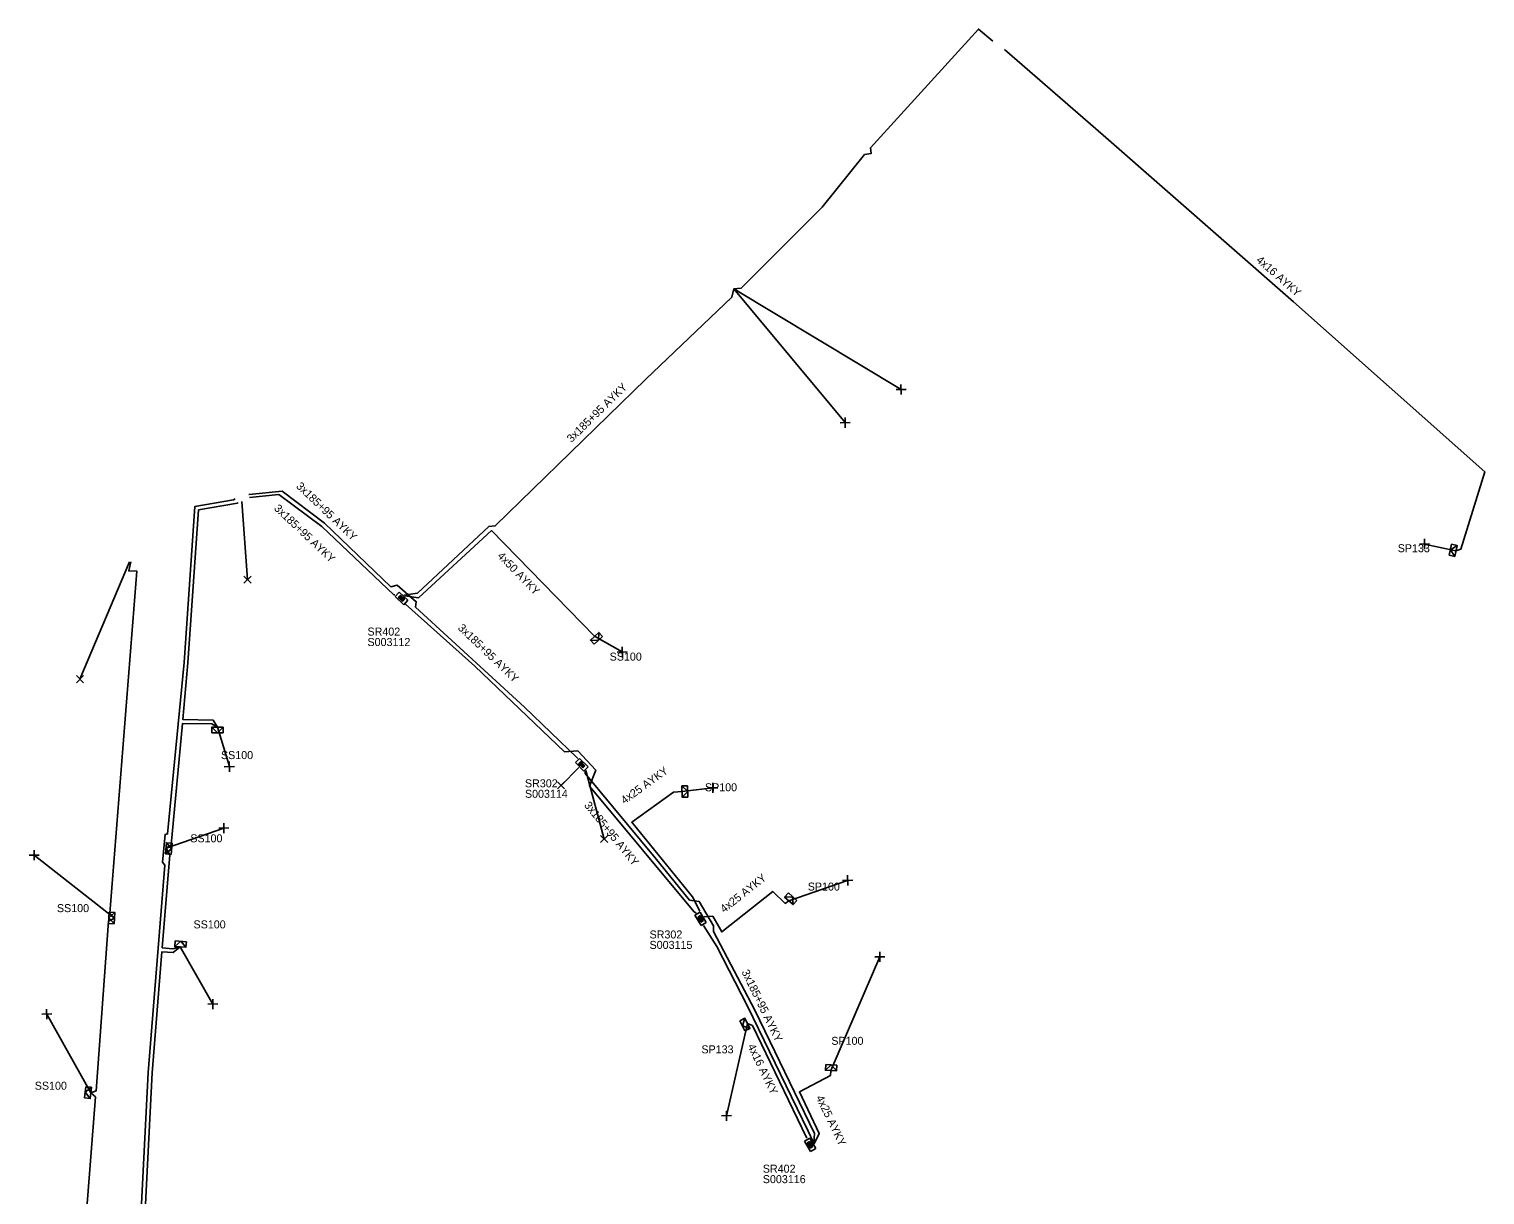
# Model space of a CAD drawing. Extents: x -762894 to -762498, y -1152897 to -1152214.
# Drawn here: x -762770.9 to -762590, y -1152359 to -1152214.1 of the extents above; entities that cross this region are included whole.
import ezdxf

# ---------------------------------------------------------------- set-up
doc = ezdxf.new("R2010")
doc.units = 0
for name, color, linetype in [('Vrstva 28', 7, 'Continuous'), ('Vrstva 29', 7, 'Continuous'), ('Vrstva 30', 7, 'Continuous'), ('Vrstva 31', 7, 'Continuous'), ('Vrstva 33', 7, 'Continuous'), ('Vrstva 34', 7, 'Continuous'), ('Vrstva 5', 7, 'Continuous'), ('Vrstva 59', 7, 'Continuous'), ('Vrstva 6', 7, 'Continuous')]:
    doc.layers.add(name, color=color, linetype=linetype)

msp = doc.modelspace()

# ---------------------------------------------------------------- linework, layer by layer
at = {"layer": 'Vrstva 28'}
for points in [[(-762724.905, -1152284.057), (-762725.416, -1152284.606)], [(-762725.416, -1152284.606), (-762724.319, -1152285.629)], [(-762724.758, -1152284.445), (-762725.015, -1152284.722)], [(-762724.755, -1152284.512), (-762724.949, -1152284.719)], [(-762723.808, -1152285.08), (-762724.905, -1152284.057)], [(-762724.753, -1152284.579), (-762724.882, -1152284.717)], [(-762724.751, -1152284.645), (-762724.815, -1152284.715)], [(-762724.213, -1152284.953), (-762724.758, -1152284.445)], [(-762724.28, -1152284.955), (-762724.755, -1152284.512)], [(-762724.347, -1152284.957), (-762724.753, -1152284.579)], [(-762724.414, -1152284.96), (-762724.751, -1152284.645)], [(-762725.015, -1152284.722), (-762724.471, -1152285.229)], [(-762724.949, -1152284.719), (-762724.473, -1152285.162)], [(-762724.882, -1152284.717), (-762724.476, -1152285.095)], [(-762724.815, -1152284.715), (-762724.478, -1152285.029)], [(-762724.753, -1152284.708), (-762724.476, -1152284.966)], [(-762724.478, -1152285.029), (-762724.414, -1152284.96)], [(-762724.476, -1152285.095), (-762724.347, -1152284.957)], [(-762724.473, -1152285.162), (-762724.28, -1152284.955)], [(-762724.471, -1152285.229), (-762724.213, -1152284.953)], [(-762724.319, -1152285.629), (-762723.808, -1152285.08)], [(-762702.486, -1152304.719), (-762703.017, -1152305.249)], [(-762703.017, -1152305.249), (-762701.956, -1152306.31)], [(-762702.353, -1152305.111), (-762702.62, -1152305.379)], [(-762702.62, -1152305.379), (-762702.094, -1152305.905)], [(-762702.353, -1152305.178), (-762702.553, -1152305.379)], [(-762702.553, -1152305.379), (-762702.094, -1152305.838)], [(-762701.426, -1152305.779), (-762702.486, -1152304.719)], [(-762702.353, -1152305.245), (-762702.486, -1152305.379)], [(-762702.486, -1152305.379), (-762702.094, -1152305.771)], [(-762702.353, -1152305.312), (-762702.419, -1152305.379)], [(-762702.419, -1152305.379), (-762702.094, -1152305.704)], [(-762702.357, -1152305.374), (-762702.09, -1152305.642)], [(-762701.826, -1152305.637), (-762702.353, -1152305.111)], [(-762701.893, -1152305.637), (-762702.353, -1152305.178)], [(-762701.96, -1152305.637), (-762702.353, -1152305.245)], [(-762702.027, -1152305.637), (-762702.353, -1152305.312)], [(-762702.094, -1152305.905), (-762701.826, -1152305.637)], [(-762702.094, -1152305.838), (-762701.893, -1152305.637)], [(-762702.094, -1152305.771), (-762701.96, -1152305.637)], [(-762702.094, -1152305.704), (-762702.027, -1152305.637)], [(-762701.956, -1152306.31), (-762701.426, -1152305.779)], [(-762687.522, -1152323.827), (-762688.165, -1152324.213)], [(-762688.165, -1152324.213), (-762687.392, -1152325.499)], [(-762687.487, -1152324.24), (-762687.811, -1152324.435)], [(-762687.811, -1152324.435), (-762687.428, -1152325.073)], [(-762687.504, -1152324.305), (-762687.746, -1152324.451)], [(-762687.52, -1152324.37), (-762687.682, -1152324.467)], [(-762687.536, -1152324.435), (-762687.617, -1152324.483)], [(-762687.299, -1152324.83), (-762687.536, -1152324.435)], [(-762686.749, -1152325.113), (-762687.522, -1152323.827)], [(-762687.234, -1152324.846), (-762687.52, -1152324.37)], [(-762687.169, -1152324.862), (-762687.504, -1152324.305)], [(-762687.104, -1152324.878), (-762687.487, -1152324.24)], [(-762687.746, -1152324.451), (-762687.412, -1152325.008)], [(-762687.682, -1152324.467), (-762687.396, -1152324.943)], [(-762687.617, -1152324.483), (-762687.38, -1152324.878)], [(-762687.555, -1152324.494), (-762687.36, -1152324.818)], [(-762687.428, -1152325.073), (-762687.104, -1152324.878)], [(-762687.412, -1152325.008), (-762687.169, -1152324.862)], [(-762687.396, -1152324.943), (-762687.234, -1152324.846)], [(-762687.392, -1152325.499), (-762686.749, -1152325.113)], [(-762687.38, -1152324.878), (-762687.299, -1152324.83)], [(-762673.901, -1152351.911), (-762674.551, -1152352.286)], [(-762674.551, -1152352.286), (-762673.801, -1152353.585)], [(-762673.874, -1152352.324), (-762674.201, -1152352.513)], [(-762674.201, -1152352.513), (-762673.829, -1152353.158)], [(-762673.891, -1152352.389), (-762674.136, -1152352.531)], [(-762674.136, -1152352.531), (-762673.812, -1152353.093)], [(-762673.908, -1152352.453), (-762674.072, -1152352.548)], [(-762674.072, -1152352.548), (-762673.794, -1152353.029)], [(-762673.925, -1152352.518), (-762674.007, -1152352.565)], [(-762674.007, -1152352.565), (-762673.777, -1152352.964)], [(-762673.946, -1152352.577), (-762673.757, -1152352.905)], [(-762673.695, -1152352.917), (-762673.925, -1152352.518)], [(-762673.631, -1152352.934), (-762673.908, -1152352.453)], [(-762673.151, -1152353.21), (-762673.901, -1152351.911)], [(-762673.566, -1152352.951), (-762673.891, -1152352.389)], [(-762673.502, -1152352.969), (-762673.874, -1152352.324)], [(-762673.829, -1152353.158), (-762673.502, -1152352.969)], [(-762673.812, -1152353.093), (-762673.566, -1152352.951)], [(-762673.801, -1152353.585), (-762673.151, -1152353.21)], [(-762673.794, -1152353.029), (-762673.631, -1152352.934)], [(-762673.777, -1152352.964), (-762673.695, -1152352.917)]]:
    msp.add_lwpolyline(points, dxfattribs=at)
at = {"layer": 'Vrstva 31'}
for points in [[(-762594.169, -1152278.107), (-762594.46, -1152279.477)], [(-762594.169, -1152278.107), (-762593.484, -1152278.253), (-762593.775, -1152279.622), (-762594.46, -1152279.477)], [(-762594.315, -1152278.792), (-762593.484, -1152278.253)], [(-762594.315, -1152278.792), (-762593.775, -1152279.622)], [(-762700.666, -1152290.531), (-762701.143, -1152290.019), (-762700.119, -1152289.064), (-762699.642, -1152289.576)], [(-762700.154, -1152290.054), (-762701.143, -1152290.019)], [(-762700.666, -1152290.531), (-762699.642, -1152289.576)], [(-762700.154, -1152290.054), (-762700.119, -1152289.064)], [(-762747.483, -1152301.55), (-762748.183, -1152300.85)], [(-762748.183, -1152301.55), (-762748.183, -1152300.85), (-762746.783, -1152300.85), (-762746.783, -1152301.55)], [(-762747.483, -1152301.55), (-762746.783, -1152300.85)], [(-762748.183, -1152301.55), (-762746.783, -1152301.55)], [(-762689.047, -1152309.541), (-762689.747, -1152309.553), (-762689.772, -1152308.153), (-762689.072, -1152308.141)], [(-762689.06, -1152308.841), (-762689.772, -1152308.153)], [(-762689.047, -1152309.541), (-762689.072, -1152308.141)], [(-762689.06, -1152308.841), (-762689.747, -1152309.553)], [(-762753.22, -1152316.65), (-762753.919, -1152316.601), (-762753.821, -1152315.205), (-762753.123, -1152315.254)], [(-762753.172, -1152315.952), (-762753.821, -1152315.205)], [(-762753.22, -1152316.65), (-762753.123, -1152315.254)], [(-762753.172, -1152315.952), (-762753.919, -1152316.601)], [(-762675.509, -1152322.38), (-762675.977, -1152322.9), (-762677.017, -1152321.963), (-762676.549, -1152321.443)], [(-762676.029, -1152321.911), (-762677.017, -1152321.963)], [(-762675.509, -1152322.38), (-762676.549, -1152321.443)], [(-762676.029, -1152321.911), (-762675.977, -1152322.9)], [(-762760.92, -1152323.83), (-762761.017, -1152325.226)], [(-762760.92, -1152323.83), (-762760.221, -1152323.879), (-762760.319, -1152325.275), (-762761.017, -1152325.226)], [(-762760.968, -1152324.528), (-762760.221, -1152323.879)], [(-762760.968, -1152324.528), (-762760.319, -1152325.275)], [(-762751.34, -1152327.501), (-762751.388, -1152328.199), (-762752.785, -1152328.101), (-762752.736, -1152327.403)], [(-762752.038, -1152327.452), (-762752.785, -1152328.101)], [(-762751.34, -1152327.501), (-762752.736, -1152327.403)], [(-762752.038, -1152327.452), (-762751.388, -1152328.199)], [(-762682.578, -1152337.325), (-762681.949, -1152337.018), (-762681.335, -1152338.277), (-762681.964, -1152338.583)], [(-762682.271, -1152337.954), (-762681.949, -1152337.018)], [(-762682.578, -1152337.325), (-762681.964, -1152338.583)], [(-762682.271, -1152337.954), (-762681.335, -1152338.277)], [(-762670.522, -1152342.847), (-762670.558, -1152343.546), (-762671.956, -1152343.473), (-762671.92, -1152342.774)], [(-762671.221, -1152342.81), (-762671.956, -1152343.473)], [(-762670.522, -1152342.847), (-762671.92, -1152342.774)], [(-762671.221, -1152342.81), (-762670.558, -1152343.546)], [(-762763.833, -1152345.528), (-762763.979, -1152346.92)], [(-762763.833, -1152345.528), (-762763.137, -1152345.601), (-762763.283, -1152346.993), (-762763.979, -1152346.92)], [(-762763.906, -1152346.224), (-762763.137, -1152345.601)], [(-762763.906, -1152346.224), (-762763.283, -1152346.993)]]:
    msp.add_lwpolyline(points, dxfattribs=at)
at = {"layer": 'Vrstva 34'}
for points in [[(-762663.185, -1152258.891), (-762661.935, -1152258.869)], [(-762662.549, -1152259.505), (-762662.571, -1152258.255)], [(-762669.489, -1152263.625), (-762669.511, -1152262.375)], [(-762670.125, -1152263.011), (-762668.875, -1152262.989)], [(-762598.165, -1152278.091), (-762596.915, -1152278.069)], [(-762597.529, -1152278.705), (-762597.551, -1152277.455)], [(-762744.192, -1152282.058), (-762743.308, -1152282.942)], [(-762744.192, -1152282.942), (-762743.308, -1152282.058)], [(-762697.815, -1152291.511), (-762696.565, -1152291.489)], [(-762697.179, -1152292.125), (-762697.201, -1152290.875)], [(-762765.002, -1152294.438), (-762764.118, -1152295.322)], [(-762765.002, -1152295.322), (-762764.118, -1152294.438)], [(-762746.625, -1152305.761), (-762745.375, -1152305.739)], [(-762745.989, -1152306.375), (-762746.011, -1152305.125)], [(-762705.232, -1152307.638), (-762704.348, -1152308.522)], [(-762705.232, -1152308.522), (-762704.348, -1152307.638)], [(-762685.929, -1152309.005), (-762685.951, -1152307.755)], [(-762686.565, -1152308.391), (-762685.315, -1152308.369)], [(-762747.315, -1152313.391), (-762746.065, -1152313.369)], [(-762746.679, -1152314.005), (-762746.701, -1152312.755)], [(-762699.882, -1152314.308), (-762698.998, -1152315.192)], [(-762699.882, -1152315.192), (-762698.998, -1152314.308)], [(-762770.875, -1152316.761), (-762769.625, -1152316.739)], [(-762770.239, -1152317.375), (-762770.261, -1152316.125)], [(-762669.815, -1152319.891), (-762668.565, -1152319.869)], [(-762669.179, -1152320.505), (-762669.201, -1152319.255)], [(-762665.815, -1152329.391), (-762664.565, -1152329.369)], [(-762665.179, -1152330.005), (-762665.201, -1152328.755)], [(-762748.685, -1152335.261), (-762747.435, -1152335.239)], [(-762748.049, -1152335.875), (-762748.071, -1152334.625)], [(-762769.315, -1152336.511), (-762768.065, -1152336.489)], [(-762768.679, -1152337.125), (-762768.701, -1152335.875)], [(-762684.875, -1152349.141), (-762683.625, -1152349.119)], [(-762684.239, -1152349.755), (-762684.261, -1152348.505)]]:
    msp.add_lwpolyline(points, dxfattribs=at)
at = {"layer": 'Vrstva 5'}
for points in [[(-762724.31, -1152284.43), (-762722.63, -1152284.17), (-762713.76, -1152275.92), (-762712.96, -1152275.83), (-762694.28, -1152257.59), (-762683.59, -1152247.42), (-762683.33, -1152246.36), (-762682.4, -1152246.27), (-762672.37, -1152236.2), (-762667.09, -1152229.67), (-762666.25, -1152229.54), (-762666.34, -1152228.83), (-762652.95, -1152214.09), (-762651.16, -1152215.6)], [(-762593.63, -1152278.94), (-762593.01, -1152278.71), (-762590.03, -1152269.13), (-762613.8, -1152248), (-762637.44, -1152227.28), (-762649.71, -1152216.61)], [(-762743.59, -1152271.94), (-762743.55, -1152271.94), (-762739.45, -1152271.5), (-762734.19, -1152275.49), (-762725.94, -1152283.39), (-762725.15, -1152283.19), (-762722.79, -1152285.26), (-762722.88, -1152285.92), (-762709.34, -1152298.37), (-762702.81, -1152304.67), (-762702.7, -1152304.75)], [(-762743.51, -1152272.3), (-762739.84, -1152271.92), (-762734.51, -1152275.92), (-762725.55, -1152284.39), (-762725.43, -1152284.41)], [(-762764.03, -1152506.05), (-762759.5, -1152504.75), (-762761.48, -1152442.16), (-762756.22, -1152442.14), (-762757.58, -1152410), (-762758.2, -1152389.39), (-762757.76, -1152376.42), (-762756.07, -1152343.75), (-762754.03, -1152318), (-762754.3, -1152317.61), (-762753.99, -1152314.18), (-762753.67, -1152314.11), (-762751.63, -1152292.79), (-762750.29, -1152273.43), (-762745.47, -1152272.59), (-762745.28, -1152272.45)], [(-762757.26, -1152376.45), (-762755.57, -1152343.78), (-762754.37, -1152328.75), (-762752.98, -1152328.86), (-762752.09, -1152328.15), (-762753.04, -1152328.37), (-762754.33, -1152328.26), (-762753.4, -1152316.72), (-762753.87, -1152315.9), (-762753.24, -1152315.45), (-762751.82, -1152300.38), (-762748.16, -1152300.43), (-762747.48, -1152300.85), (-762748.01, -1152299.98), (-762751.78, -1152299.87), (-762751.14, -1152292.83), (-762749.82, -1152273.85), (-762744.97, -1152272.99), (-762744.93, -1152272.91)], [(-762700.63, -1152289.54), (-762713.45, -1152276.41), (-762722.49, -1152284.75), (-762724.22, -1152284.52)], [(-762758.23, -1152280.29), (-762758.49, -1152281.43), (-762757.51, -1152281.45), (-762760.85, -1152323.96), (-762760.28, -1152324.58), (-762761, -1152324.96), (-762762.54, -1152346.03), (-762763.21, -1152346.3), (-762762.63, -1152346.79), (-762764.22, -1152366.95)], [(-762724.1, -1152285.57), (-762715.49, -1152293.27), (-762704.35, -1152303.92), (-762702.71, -1152303.79), (-762700.49, -1152306.18), (-762701.25, -1152308.18), (-762688.3, -1152323.76), (-762687.99, -1152323.95)], [(-762673.41, -1152352.5), (-762673.3, -1152351.32), (-762680.71, -1152336), (-762685.86, -1152326.24), (-762685.86, -1152325.53), (-762687.63, -1152322.51), (-762688.83, -1152322.34), (-762693.09, -1152317.1), (-762701.78, -1152306.58), (-762701.81, -1152306.35)], [(-762689.76, -1152308.85), (-762690.82, -1152308.93), (-762696.01, -1152312.66), (-762688.47, -1152321.94), (-762687.55, -1152323.69)], [(-762676.5, -1152322.43), (-762676.94, -1152322.74), (-762678.49, -1152321.27), (-762684.84, -1152326.29), (-762685.95, -1152324.33), (-762687.03, -1152324.4)], [(-762673.48, -1152352.38), (-762674.1, -1152351.05), (-762681.64, -1152335.52), (-762685.46, -1152328.11), (-762687.09, -1152325.47)], [(-762674.22, -1152351.94), (-762674.32, -1152351.85), (-762681.02, -1152337.91), (-762681.64, -1152337.65)], [(-762671.26, -1152343.51), (-762671.32, -1152344.13), (-762675.18, -1152346.17), (-762672.72, -1152351.32), (-762673.35, -1152352.61)]]:
    msp.add_lwpolyline(points, dxfattribs=at)
at = {"layer": 'Vrstva 59'}
for points in [[(-762683.33, -1152246.36), (-762662.56, -1152258.88)], [(-762683.33, -1152246.36), (-762669.5, -1152263)], [(-762744.43, -1152272.81), (-762743.75, -1152282.5)], [(-762593.63, -1152278.94), (-762597.54, -1152278.08)], [(-762758.39, -1152280.3), (-762764.56, -1152294.88)], [(-762700.63, -1152289.54), (-762697.19, -1152291.5)], [(-762747.48, -1152300.85), (-762746, -1152305.75)], [(-762702.58, -1152305.87), (-762704.79, -1152308.08)], [(-762701.7, -1152306.23), (-762699.44, -1152314.75)], [(-762689.76, -1152308.85), (-762685.94, -1152308.38)], [(-762753.87, -1152315.9), (-762746.69, -1152313.38)], [(-762760.28, -1152324.58), (-762770.25, -1152316.75)], [(-762676.5, -1152322.43), (-762669.19, -1152319.88)], [(-762752.09, -1152328.15), (-762748.06, -1152335.25)], [(-762671.26, -1152343.51), (-762665.19, -1152329.38)], [(-762763.21, -1152346.3), (-762768.69, -1152336.5)], [(-762681.64, -1152337.65), (-762684.25, -1152349.13)]]:
    msp.add_lwpolyline(points, dxfattribs=at)

# ---------------------------------------------------------------- texts
at = {"layer": 'Vrstva 29'}
for s, p in [('S003112', (-762728.84, -1152290.76)), ('S003114', (-762709.28, -1152309.62)), ('S003115', (-762693.8, -1152328.4)), ('S003116', (-762679.73, -1152357.51))]:
    msp.add_text(s, height=0.9943, dxfattribs=at).set_placement(p)
at = {"layer": 'Vrstva 30'}
for s, p in [('SR402', (-762728.84, -1152289.46)), ('SR302', (-762709.28, -1152308.32)), ('SR302', (-762693.8, -1152327.1)), ('SR402', (-762679.73, -1152356.21))]:
    msp.add_text(s, height=0.9943, dxfattribs=at).set_placement(p)
at = {"layer": 'Vrstva 33'}
for s, p in [('SP133', (-762600.86, -1152279.1)), ('SS100', (-762698.76, -1152292.57)), ('SS100', (-762747.04, -1152304.81)), ('SP100', (-762686.92, -1152308.81)), ('SS100', (-762750.85, -1152315.15)), ('SP100', (-762674.15, -1152321.15)), ('SS100', (-762767.42, -1152323.83)), ('SS100', (-762750.45, -1152325.85)), ('SP133', (-762687.36, -1152341.38)), ('SP100', (-762671.22, -1152340.32)), ('SS100', (-762770.17, -1152345.9))]:
    msp.add_text(s, height=0.9943, dxfattribs=at).set_placement(p)
at = {"layer": 'Vrstva 6'}
for s, height, rotation, p in [('4x16 AYKY', 0.9943, 318.76016, (-762618.52, -1152242.92)), ('3x185+95 AYKY', 0.99428, 44.32789, (-762703.5, -1152265.53)), ('3x185+95 AYKY', 0.99429, 316.24255, (-762737.78, -1152270.99)), ('3x185+95 AYKY', 0.99429, 316.58679, (-762740.53, -1152273.75)), ('4x50 AYKY', 0.9943, 314.2957, (-762712.78, -1152279.64)), ('3x185+95 AYKY', 0.99429, 316.2669, (-762717.69, -1152288.61)), ('4x25 AYKY', 0.9943, 35.69206, (-762696.92, -1152310.45)), ('3x185+95 AYKY', 0.99428, 309.11423, (-762701.99, -1152310.58)), ('4x25 AYKY', 0.9943, 38.3322, (-762684.53, -1152323.97)), ('3x185+95 AYKY', 0.99429, 295.89353, (-762682.4, -1152331.25)), ('4x16 AYKY', 0.9943, 295.66962, (-762681.65, -1152340.48)), ('4x25 AYKY', 0.9943, 295.55585, (-762673.15, -1152346.87))]:
    msp.add_text(s, height=height, rotation=rotation, dxfattribs=at).set_placement(p)

doc.saveas('drawing.dxf')
